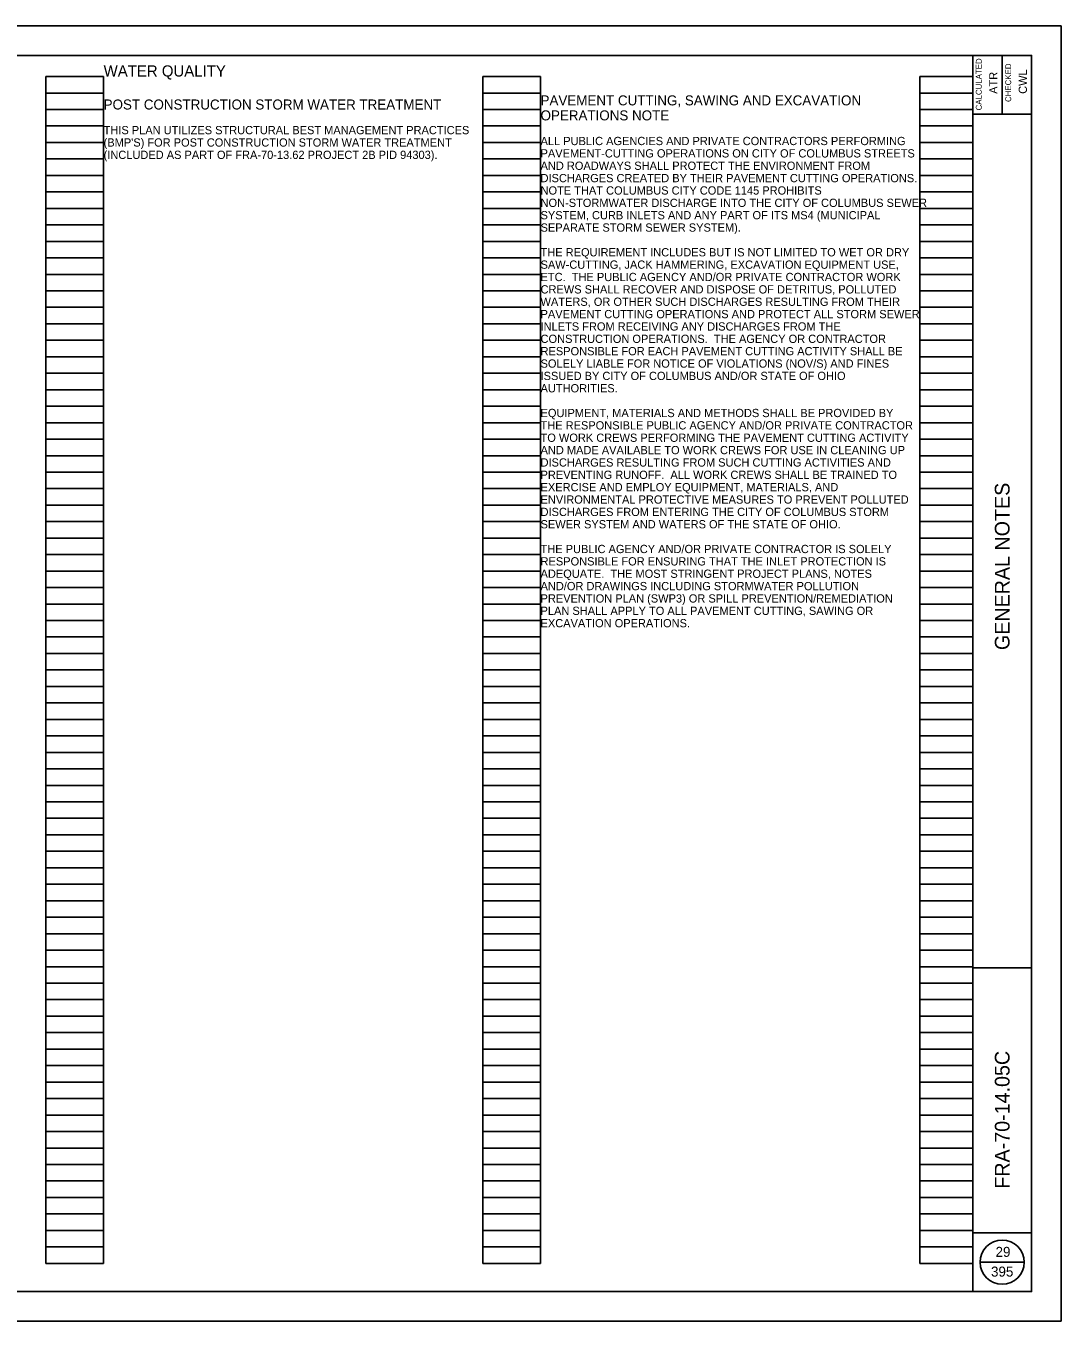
# Model space of a CAD drawing. Extents: x 0 to 34, y 0 to 22.
# Drawn here: x 16.42 to 34, y 0 to 22 of the extents above; entities that cross this region are included whole.
import ezdxf

# ---------------------------------------------------------------- set-up
doc = ezdxf.new("R2010")
doc.units = 0
for name, color, linetype in [('SC_Scratch1', 7, 'Continuous'), ('SH_Border', 7, 'Continuous'), ('SH_Cut_Line', 7, 'Continuous'), ('SH_Data', 7, 'Continuous'), ('SH_Text', 7, 'Continuous'), ('TX_P_1', 7, 'Continuous')]:
    doc.layers.add(name, color=color, linetype=linetype)

msp = doc.modelspace()

# ---------------------------------------------------------------- linework, layer by layer
at = {"layer": 'SC_Scratch1'}
for p, q in [((16.76, 0.98), (16.76, 21.14)), ((16.76, 21.14), (17.74, 21.14)), ((17.74, 0.98), (17.74, 21.14)), ((24.18, 0.98), (24.18, 21.14)), ((24.18, 21.14), (25.16, 21.14)), ((25.16, 0.98), (25.16, 21.14)), ((31.6, 0.98), (31.6, 21.14)), ((31.6, 21.14), (32.5, 21.14)), ((32.5, 0.98), (32.5, 21.14)), ((16.76, 20.86), (17.74, 20.86)), ((24.18, 20.86), (25.16, 20.86)), ((31.6, 20.86), (32.5, 20.86)), ((16.76, 20.58), (17.74, 20.58)), ((24.18, 20.58), (25.16, 20.58)), ((31.6, 20.58), (32.5, 20.58)), ((16.76, 20.3), (17.74, 20.3)), ((24.18, 20.3), (25.16, 20.3)), ((31.6, 20.3), (32.5, 20.3)), ((16.76, 20.02), (17.74, 20.02)), ((24.18, 20.02), (25.16, 20.02)), ((31.6, 20.02), (32.5, 20.02)), ((16.76, 19.74), (17.74, 19.74)), ((24.18, 19.74), (25.16, 19.74)), ((31.6, 19.74), (32.5, 19.74)), ((16.76, 19.46), (17.74, 19.46)), ((24.18, 19.46), (25.16, 19.46)), ((31.6, 19.46), (32.5, 19.46)), ((16.76, 19.18), (17.74, 19.18)), ((24.18, 19.18), (25.16, 19.18)), ((31.6, 19.18), (32.5, 19.18)), ((16.76, 18.9), (17.74, 18.9)), ((24.18, 18.9), (25.16, 18.9)), ((31.6, 18.9), (32.5, 18.9)), ((16.76, 18.62), (17.74, 18.62)), ((24.18, 18.62), (25.16, 18.62)), ((31.6, 18.62), (32.5, 18.62)), ((16.76, 18.34), (17.74, 18.34)), ((24.18, 18.34), (25.16, 18.34)), ((31.6, 18.34), (32.5, 18.34)), ((16.76, 18.06), (17.74, 18.06)), ((24.18, 18.06), (25.16, 18.06)), ((31.6, 18.06), (32.5, 18.06)), ((16.76, 17.78), (17.74, 17.78)), ((24.18, 17.78), (25.16, 17.78)), ((31.6, 17.78), (32.5, 17.78)), ((16.76, 17.5), (17.74, 17.5)), ((24.18, 17.5), (25.16, 17.5)), ((31.6, 17.5), (32.5, 17.5)), ((16.76, 17.22), (17.74, 17.22)), ((24.18, 17.22), (25.16, 17.22)), ((31.6, 17.22), (32.5, 17.22)), ((16.76, 16.94), (17.74, 16.94)), ((24.18, 16.94), (25.16, 16.94)), ((31.6, 16.94), (32.5, 16.94)), ((16.76, 16.66), (17.74, 16.66)), ((24.18, 16.66), (25.16, 16.66)), ((31.6, 16.66), (32.5, 16.66)), ((16.76, 16.38), (17.74, 16.38)), ((24.18, 16.38), (25.16, 16.38)), ((31.6, 16.38), (32.5, 16.38)), ((16.76, 16.1), (17.74, 16.1)), ((24.18, 16.1), (25.16, 16.1)), ((31.6, 16.1), (32.5, 16.1)), ((16.76, 15.82), (17.74, 15.82)), ((24.18, 15.82), (25.16, 15.82)), ((31.6, 15.82), (32.5, 15.82)), ((16.76, 15.54), (17.74, 15.54)), ((24.18, 15.54), (25.16, 15.54)), ((31.6, 15.54), (32.5, 15.54)), ((16.76, 15.26), (17.74, 15.26)), ((24.18, 15.26), (25.16, 15.26)), ((31.6, 15.26), (32.5, 15.26)), ((16.76, 14.98), (17.74, 14.98)), ((24.18, 14.98), (25.16, 14.98)), ((31.6, 14.98), (32.5, 14.98)), ((16.76, 14.7), (17.74, 14.7)), ((24.18, 14.7), (25.16, 14.7)), ((31.6, 14.7), (32.5, 14.7)), ((16.76, 14.42), (17.74, 14.42)), ((24.18, 14.42), (25.16, 14.42)), ((31.6, 14.42), (32.5, 14.42)), ((16.76, 14.14), (17.74, 14.14)), ((24.18, 14.14), (25.16, 14.14)), ((31.6, 14.14), (32.5, 14.14)), ((16.76, 13.86), (17.74, 13.86)), ((24.18, 13.86), (25.16, 13.86)), ((31.6, 13.86), (32.5, 13.86)), ((16.76, 13.58), (17.74, 13.58)), ((24.18, 13.58), (25.16, 13.58)), ((31.6, 13.58), (32.5, 13.58)), ((16.76, 13.3), (17.74, 13.3)), ((24.18, 13.3), (25.16, 13.3)), ((31.6, 13.3), (32.5, 13.3)), ((16.76, 13.02), (17.74, 13.02)), ((24.18, 13.02), (25.16, 13.02)), ((31.6, 13.02), (32.5, 13.02)), ((16.76, 12.74), (17.74, 12.74)), ((24.18, 12.74), (25.16, 12.74)), ((31.6, 12.74), (32.5, 12.74)), ((16.76, 12.46), (17.74, 12.46)), ((24.18, 12.46), (25.16, 12.46)), ((31.6, 12.46), (32.5, 12.46)), ((16.76, 12.18), (17.74, 12.18)), ((24.18, 12.18), (25.16, 12.18)), ((31.6, 12.18), (32.5, 12.18)), ((16.76, 11.9), (17.74, 11.9)), ((24.18, 11.9), (25.16, 11.9)), ((31.6, 11.9), (32.5, 11.9)), ((16.76, 11.62), (17.74, 11.62)), ((24.18, 11.62), (25.16, 11.62)), ((31.6, 11.62), (32.5, 11.62)), ((16.76, 11.34), (17.74, 11.34)), ((24.18, 11.34), (25.16, 11.34)), ((31.6, 11.34), (32.5, 11.34)), ((16.76, 11.06), (17.74, 11.06)), ((24.18, 11.06), (25.16, 11.06)), ((31.6, 11.06), (32.5, 11.06)), ((16.76, 10.78), (17.74, 10.78)), ((24.18, 10.78), (25.16, 10.78)), ((31.6, 10.78), (32.5, 10.78)), ((16.76, 10.5), (17.74, 10.5)), ((24.18, 10.5), (25.16, 10.5)), ((31.6, 10.5), (32.5, 10.5)), ((16.76, 10.22), (17.74, 10.22)), ((24.18, 10.22), (25.16, 10.22)), ((31.6, 10.22), (32.5, 10.22)), ((16.76, 9.94), (17.74, 9.94)), ((24.18, 9.94), (25.16, 9.94)), ((31.6, 9.94), (32.5, 9.94)), ((16.76, 9.66), (17.74, 9.66)), ((24.18, 9.66), (25.16, 9.66)), ((31.6, 9.66), (32.5, 9.66)), ((16.76, 9.38), (17.74, 9.38)), ((24.18, 9.38), (25.16, 9.38)), ((31.6, 9.38), (32.5, 9.38)), ((16.76, 9.1), (17.74, 9.1)), ((24.18, 9.1), (25.16, 9.1)), ((31.6, 9.1), (32.5, 9.1)), ((16.76, 8.82), (17.74, 8.82)), ((24.18, 8.82), (25.16, 8.82)), ((31.6, 8.82), (32.5, 8.82)), ((16.76, 8.54), (17.74, 8.54)), ((24.18, 8.54), (25.16, 8.54)), ((31.6, 8.54), (32.5, 8.54)), ((16.76, 8.26), (17.74, 8.26)), ((24.18, 8.26), (25.16, 8.26)), ((31.6, 8.26), (32.5, 8.26)), ((16.76, 7.98), (17.74, 7.98)), ((24.18, 7.98), (25.16, 7.98)), ((31.6, 7.98), (32.5, 7.98)), ((16.76, 7.7), (17.74, 7.7)), ((24.18, 7.7), (25.16, 7.7)), ((31.6, 7.7), (32.5, 7.7)), ((16.76, 7.42), (17.74, 7.42)), ((24.18, 7.42), (25.16, 7.42)), ((31.6, 7.42), (32.5, 7.42)), ((16.76, 7.14), (17.74, 7.14)), ((24.18, 7.14), (25.16, 7.14)), ((31.6, 7.14), (32.5, 7.14)), ((16.76, 6.86), (17.74, 6.86)), ((24.18, 6.86), (25.16, 6.86)), ((31.6, 6.86), (32.5, 6.86)), ((16.76, 6.58), (17.74, 6.58)), ((24.18, 6.58), (25.16, 6.58)), ((31.6, 6.58), (32.5, 6.58)), ((16.76, 6.3), (17.74, 6.3)), ((24.18, 6.3), (25.16, 6.3)), ((31.6, 6.3), (32.5, 6.3)), ((16.76, 6.02), (17.74, 6.02)), ((24.18, 6.02), (25.16, 6.02)), ((31.6, 6.02), (32.5, 6.02)), ((16.76, 5.74), (17.74, 5.74)), ((24.18, 5.74), (25.16, 5.74)), ((31.6, 5.74), (32.5, 5.74)), ((16.76, 5.46), (17.74, 5.46)), ((24.18, 5.46), (25.16, 5.46)), ((31.6, 5.46), (32.5, 5.46)), ((16.76, 5.18), (17.74, 5.18)), ((24.18, 5.18), (25.16, 5.18)), ((31.6, 5.18), (32.5, 5.18)), ((16.76, 4.9), (17.74, 4.9)), ((24.18, 4.9), (25.16, 4.9)), ((31.6, 4.9), (32.5, 4.9)), ((16.76, 4.62), (17.74, 4.62)), ((24.18, 4.62), (25.16, 4.62)), ((31.6, 4.62), (32.5, 4.62)), ((16.76, 4.34), (17.74, 4.34)), ((24.18, 4.34), (25.16, 4.34)), ((31.6, 4.34), (32.5, 4.34)), ((16.76, 4.06), (17.74, 4.06)), ((24.18, 4.06), (25.16, 4.06)), ((31.6, 4.06), (32.5, 4.06)), ((16.76, 3.78), (17.74, 3.78)), ((24.18, 3.78), (25.16, 3.78)), ((31.6, 3.78), (32.5, 3.78)), ((16.76, 3.5), (17.74, 3.5)), ((24.18, 3.5), (25.16, 3.5)), ((31.6, 3.5), (32.5, 3.5)), ((16.76, 3.22), (17.74, 3.22)), ((24.18, 3.22), (25.16, 3.22)), ((31.6, 3.22), (32.5, 3.22)), ((16.76, 2.94), (17.74, 2.94)), ((24.18, 2.94), (25.16, 2.94)), ((31.6, 2.94), (32.5, 2.94)), ((16.76, 2.66), (17.74, 2.66)), ((24.18, 2.66), (25.16, 2.66)), ((31.6, 2.66), (32.5, 2.66)), ((16.76, 2.38), (17.74, 2.38)), ((24.18, 2.38), (25.16, 2.38)), ((31.6, 2.38), (32.5, 2.38)), ((16.76, 2.1), (17.74, 2.1)), ((24.18, 2.1), (25.16, 2.1)), ((31.6, 2.1), (32.5, 2.1)), ((16.76, 1.82), (17.74, 1.82)), ((24.18, 1.82), (25.16, 1.82)), ((31.6, 1.82), (32.5, 1.82)), ((16.76, 1.54), (17.74, 1.54)), ((24.18, 1.54), (25.16, 1.54)), ((31.6, 1.54), (32.5, 1.54)), ((16.76, 1.26), (17.74, 1.26)), ((24.18, 1.26), (25.16, 1.26)), ((31.6, 1.26), (32.5, 1.26)), ((16.76, 0.98), (17.74, 0.98)), ((24.18, 0.98), (25.16, 0.98)), ((31.6, 0.98), (32.5, 0.98))]:
    msp.add_line(p, q, dxfattribs=at)
at = {"layer": 'SH_Border'}
for p, q in [((32.5, 0.5), (32.5, 21.5)), ((33, 21.5), (33, 20.5)), ((32.5, 20.5), (33.5, 20.5)), ((32.5, 6), (33.5, 6)), ((32.5, 1.5), (33.5, 1.5))]:
    msp.add_line(p, q, dxfattribs=at)
msp.add_lwpolyline([(2, 21.5), (33.5, 21.5), (33.5, 0.5), (2, 0.5)], close=True, dxfattribs=at)
at = {"layer": 'SH_Cut_Line'}
msp.add_lwpolyline([(0, 0), (34, 0), (34, 22), (0, 22)], close=True, dxfattribs=at)
at = {"layer": 'SH_Data'}
msp.add_line((32.625, 1), (33.375, 1), dxfattribs=at)
msp.add_circle((33, 1), 0.375, dxfattribs=at)

# ---------------------------------------------------------------- texts
for s, height, p in [('CALCULATED', 0.1, (32.652, 20.565)), ('CHECKED', 0.1, (33.152, 20.708)), ('ATR', 0.14, (32.92, 20.846)), ('CWL', 0.14, (33.42, 20.846)), ('GENERAL NOTES', 0.25, (33.125, 11.398)), ('FRA-70-14.05C', 0.25, (33.125, 2.249))]:
    msp.add_text(s, height=height, rotation=90, dxfattribs=at).set_placement(p)
for s, p in [('29', (32.887, 1.091)), ('395', (32.81, 0.756))]:
    msp.add_text(s, height=0.17, dxfattribs=at).set_placement(p)
at = {"layer": 'SH_Text'}
for s, p in [('THIS PLAN UTILIZES STRUCTURAL BEST MANAGEMENT PRACTICES', (17.74, 20.16)), ("(BMP'S) FOR POST CONSTRUCTION STORM WATER TREATMENT ", (17.74, 19.95)), ('ALL PUBLIC AGENCIES AND PRIVATE CONTRACTORS PERFORMING ', (25.16, 19.975)), ('(INCLUDED AS PART OF FRA-70-13.62 PROJECT 2B PID 94303).', (17.74, 19.74)), ('PAVEMENT-CUTTING OPERATIONS ON CITY OF COLUMBUS STREETS ', (25.16, 19.765)), ('AND ROADWAYS SHALL PROTECT THE ENVIRONMENT FROM ', (25.16, 19.555)), ('DISCHARGES CREATED BY THEIR PAVEMENT CUTTING OPERATIONS.  ', (25.16, 19.345)), ('NOTE THAT COLUMBUS CITY CODE 1145 PROHIBITS ', (25.16, 19.135)), ('NON-STORMWATER DISCHARGE INTO THE CITY OF COLUMBUS SEWER ', (25.16, 18.925)), ('SYSTEM, CURB INLETS AND ANY PART OF ITS MS4 (MUNICIPAL ', (25.16, 18.715)), ('SEPARATE STORM SEWER SYSTEM).  ', (25.16, 18.505)), ('THE REQUIREMENT INCLUDES BUT IS NOT LIMITED TO WET OR DRY ', (25.16, 18.085)), ('SAW-CUTTING, JACK HAMMERING, EXCAVATION EQUIPMENT USE, ', (25.16, 17.875)), ('ETC.  THE PUBLIC AGENCY AND/OR PRIVATE CONTRACTOR WORK ', (25.16, 17.665)), ('WATERS, OR OTHER SUCH DISCHARGES RESULTING FROM THEIR ', (25.16, 17.245)), ('CREWS SHALL RECOVER AND DISPOSE OF DETRITUS, POLLUTED ', (25.16, 17.455)), ('PAVEMENT CUTTING OPERATIONS AND PROTECT ALL STORM SEWER ', (25.16, 17.035)), ('INLETS FROM RECEIVING ANY DISCHARGES FROM THE ', (25.16, 16.825)), ('CONSTRUCTION OPERATIONS.  THE AGENCY OR CONTRACTOR ', (25.16, 16.615)), ('RESPONSIBLE FOR EACH PAVEMENT CUTTING ACTIVITY SHALL BE ', (25.16, 16.405)), ('SOLELY LIABLE FOR NOTICE OF VIOLATIONS (NOV/S) AND FINES ', (25.16, 16.195)), ('ISSUED BY CITY OF COLUMBUS AND/OR STATE OF OHIO ', (25.16, 15.985)), ('AUTHORITIES.  ', (25.16, 15.775)), ('EQUIPMENT, MATERIALS AND METHODS SHALL BE PROVIDED BY ', (25.16, 15.355)), ('THE RESPONSIBLE PUBLIC AGENCY AND/OR PRIVATE CONTRACTOR ', (25.16, 15.145)), ('TO WORK CREWS PERFORMING THE PAVEMENT CUTTING ACTIVITY ', (25.16, 14.935)), ('AND MADE AVAILABLE TO WORK CREWS FOR USE IN CLEANING UP ', (25.16, 14.725)), ('DISCHARGES RESULTING FROM SUCH CUTTING ACTIVITIES AND ', (25.16, 14.515)), ('PREVENTING RUNOFF.  ALL WORK CREWS SHALL BE TRAINED TO ', (25.16, 14.305)), ('EXERCISE AND EMPLOY EQUIPMENT, MATERIALS, AND ', (25.16, 14.095)), ('ENVIRONMENTAL PROTECTIVE MEASURES TO PREVENT POLLUTED ', (25.16, 13.885)), ('DISCHARGES FROM ENTERING THE CITY OF COLUMBUS STORM ', (25.16, 13.675)), ('SEWER SYSTEM AND WATERS OF THE STATE OF OHIO.  ', (25.16, 13.465)), ('THE PUBLIC AGENCY AND/OR PRIVATE CONTRACTOR IS SOLELY ', (25.16, 13.045)), ('ADEQUATE.  THE MOST STRINGENT PROJECT PLANS, NOTES ', (25.16, 12.625)), ('RESPONSIBLE FOR ENSURING THAT THE INLET PROTECTION IS ', (25.16, 12.835)), ('AND/OR DRAWINGS INCLUDING STORMWATER POLLUTION ', (25.16, 12.415)), ('PREVENTION PLAN (SWP3) OR SPILL PREVENTION/REMEDIATION ', (25.16, 12.205)), ('PLAN SHALL APPLY TO ALL PAVEMENT CUTTING, SAWING OR ', (25.16, 11.995)), ('EXCAVATION OPERATIONS.  ', (25.16, 11.785))]:
    msp.add_text(s, height=0.14, dxfattribs=at).set_placement(p)
at = {"layer": 'TX_P_1'}
for s, height, p in [('WATER QUALITY', 0.19, (17.74, 21.14)), ('POST CONSTRUCTION STORM WATER TREATMENT', 0.17, (17.74, 20.58)), ('PAVEMENT CUTTING, SAWING AND EXCAVATION ', 0.17, (25.16, 20.65)), ('OPERATIONS NOTE', 0.17, (25.16, 20.395))]:
    msp.add_text(s, height=height, dxfattribs=at).set_placement(p)

doc.saveas('drawing.dxf')
